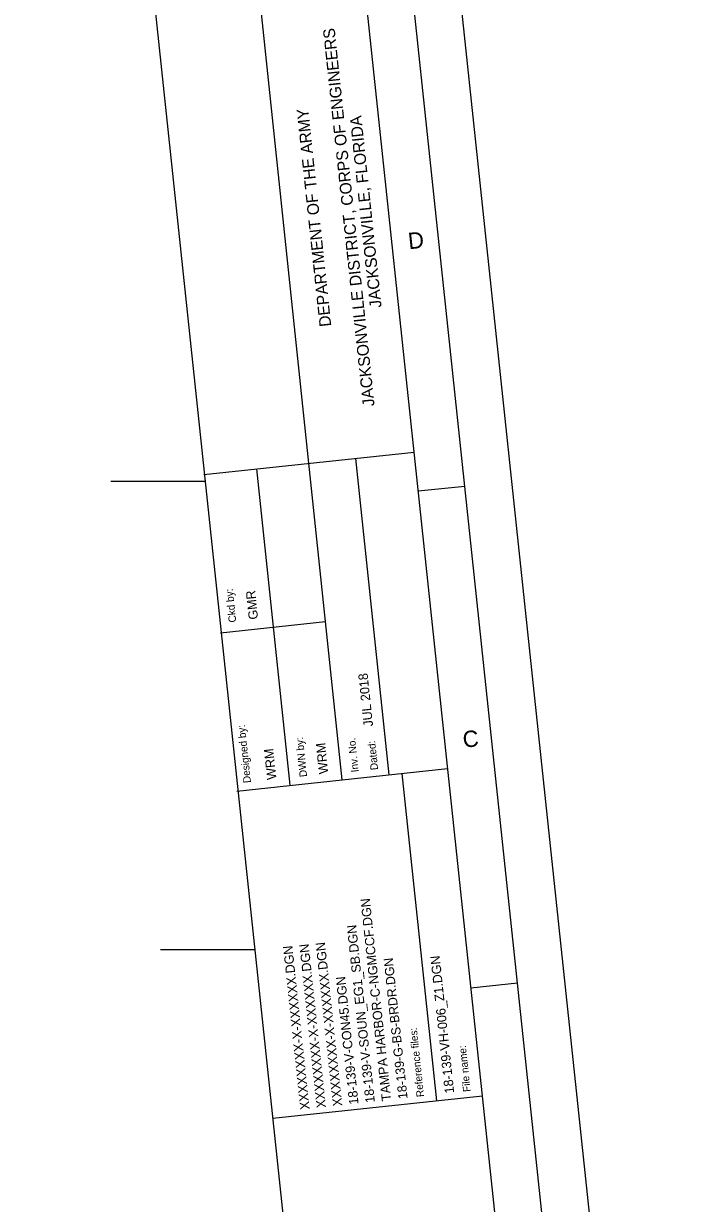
# Model space of a CAD drawing. Extents: x 347441 to 352175, y 1184845 to 1188690.
# Drawn here: x 351475 to 352175, y 1186229 to 1187488 of the extents above; entities that cross this region are included whole.
import ezdxf

# ---------------------------------------------------------------- set-up
doc = ezdxf.new("R2010")
doc.units = 0
for name, color, linetype in [('G-ANNO-NPLT', 7, 'Continuous'), ('G-ANNO-TEXT-DRWG', 7, 'Continuous'), ('G-ANNO-TEXT-PROJ', 7, 'Continuous'), ('G-ANNO-TEXT-TTLB', 7, 'Continuous'), ('G-ANNO-TTLB', 7, 'Continuous'), ('V-TOPO-COOR-STAT', 7, 'Continuous')]:
    doc.layers.add(name, color=color, linetype=linetype)

msp = doc.modelspace()

# ---------------------------------------------------------------- linework, layer by layer
at = {"layer": 'G-ANNO-NPLT'}
msp.add_lwpolyline([(347441.2, 1188226.4), (351816.7, 1188690.2), (352175, 1185309.2), (347799.6, 1184845.4)], close=True, dxfattribs=at)
at = {"layer": 'G-ANNO-TTLB'}
for p, q in [((351504, 1188556.5), (351841.3, 1185374.4)), ((351815.3, 1186681.1), (351725.3, 1187535.9)), ((351667.5, 1187007), (351892, 1187030.8)), ((351829.4, 1187024.1), (351865.2, 1186686.3)), ((351759.6, 1186675.2), (351724.1, 1187013)), ((351946.1, 1186994.3), (351896.4, 1186989.1)), ((351685.4, 1186838.1), (351797.5, 1186849.9)), ((351702.9, 1186669.1), (351927.8, 1186693)), ((351878.8, 1186687.8), (351915.8, 1186338.4)), ((352002.4, 1186464), (351952.6, 1186458.7)), ((351741.1, 1186319.8), (351964.8, 1186343.6))]:
    msp.add_line(p, q, dxfattribs=at)
for points in [[(347844, 1184900.4), (352120.1, 1185353.6), (351772.2, 1188635.2), (347496.2, 1188182)], [(351727.8, 1188580.2), (347625.8, 1188145.4), (347963.1, 1184963.3), (352065.1, 1185398.1)]]:
    msp.add_lwpolyline(points, close=True, dxfattribs=at)
at = {"layer": 'V-TOPO-COOR-STAT'}
for p, q in [((351568.4, 1187000), (351669, 1187000)), ((351621.4, 1186500), (351722, 1186500))]:
    msp.add_line(p, q, dxfattribs=at)

# ---------------------------------------------------------------- texts
at = {"layer": 'G-ANNO-TEXT-DRWG'}
for s, p in [('GMR', (351725.6, 1186852.7)), ('WRM', (351745.2, 1186681.7)), ('WRM', (351800.5, 1186687.8)), ('TAMPA HARBOR-C-NGMCCF.DGN', (351867.6, 1186338.6)), ('18-139-V-SOUN_EG1_SB.DGN', (351850.2, 1186336.8)), ('XXXXXXXX-X-XXXXXX.DGN', (351780.6, 1186329.4)), ('XXXXXXXX-X-XXXXXX.DGN', (351798, 1186331.3)), ('XXXXXXXX-X-XXXXXX.DGN', (351815.4, 1186333.1)), ('18-139-VH-006_Z1.DGN', (351934.8, 1186346.8)), ('18-139-V-CON45.DGN', (351832.8, 1186334.9))]:
    msp.add_text(s, height=10, rotation=96.0506, dxfattribs=at).set_placement(p)
at = {"layer": 'G-ANNO-TEXT-PROJ'}
for s, height, p in [('JUL 2018', 10, (351848.3, 1186738.4)), ('18-139-G-BS-BRDR.DGN', 9.8, (351885.1, 1186340.9))]:
    msp.add_text(s, height=height, rotation=96.0506, dxfattribs=at).set_placement(p)
at = {"layer": 'G-ANNO-TEXT-TTLB'}
for s, height, p in [('JACKSONVILLE DISTRICT, CORPS OF ENGINEERS', 12.5, (351849.9, 1187080.3)), ('DEPARTMENT OF THE ARMY', 12.5, (351803.7, 1187165.3)), ('JACKSONVILLE, FLORIDA', 12.5, (351857.4, 1187185.5)), ('Ckd by:', 8, (351702.3, 1186849.4)), ('Designed by:', 8, (351718, 1186678)), ('DWN by:', 8, (351777.9, 1186684.4)), ('Inv. No.', 8, (351832.9, 1186689.5)), ('Dated:', 8, (351853.6, 1186691.8)), ('Reference files:', 8, (351902.7, 1186342.8)), ('File name:', 8, (351952.4, 1186348.3))]:
    msp.add_text(s, height=height, rotation=96.0506, dxfattribs=at).set_placement(p)
at = {"layer": 'G-ANNO-TTLB'}
for s, p in [('D', (351886.5, 1187247.3)), ('C', (351944.8, 1186715.2))]:
    msp.add_text(s, height=17.5, rotation=6.0506, dxfattribs=at).set_placement(p)

doc.saveas('drawing.dxf')
